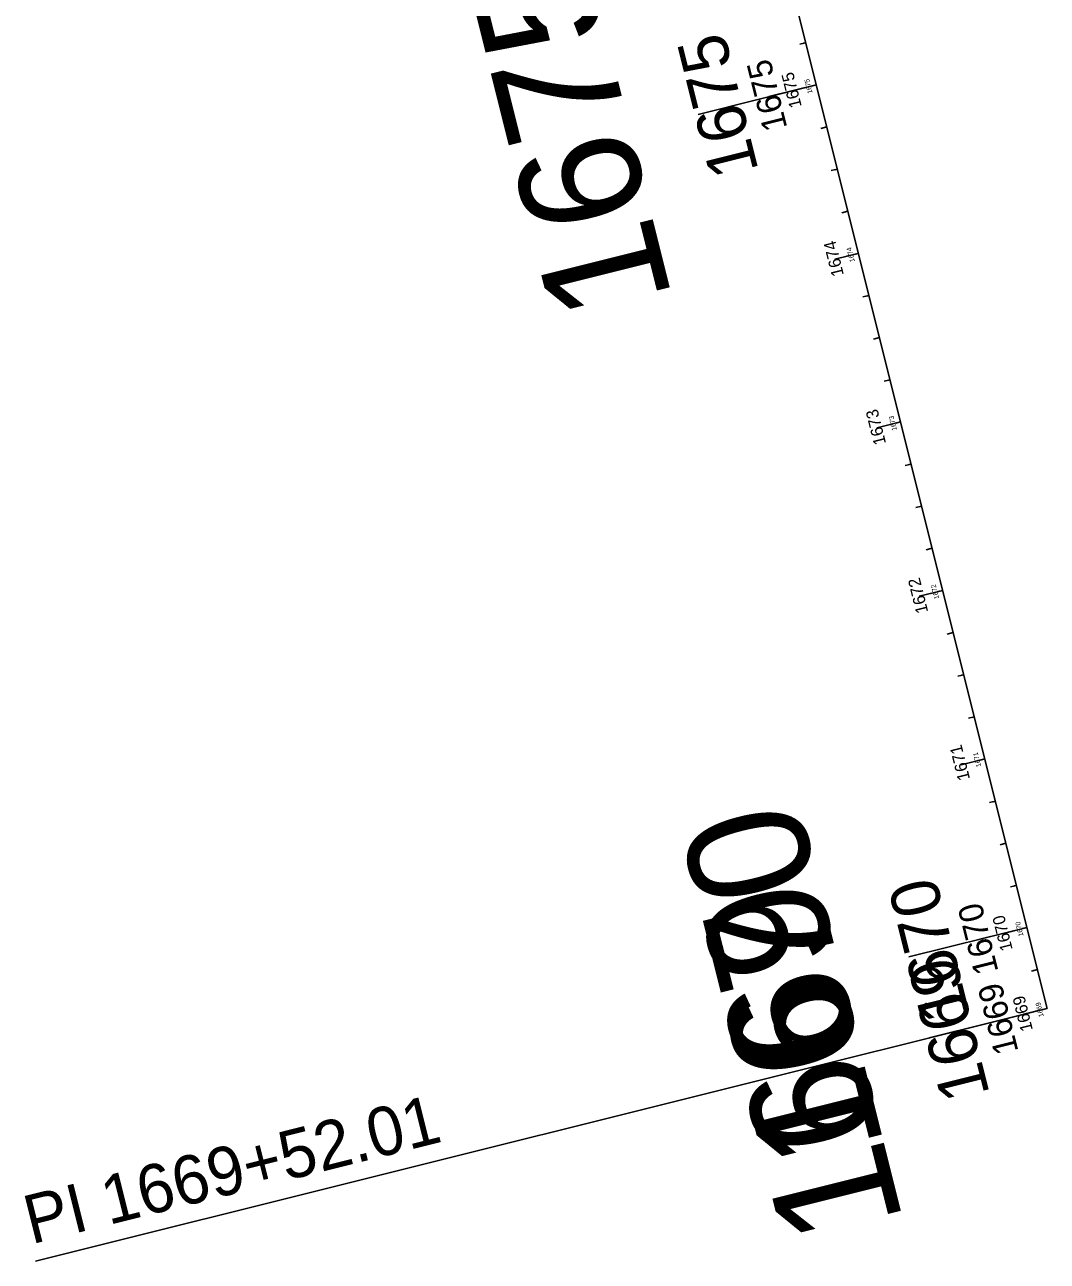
# Model space of a CAD drawing. Extents: x 353835 to 363333, y 126218 to 205387.
# Drawn here: x 361909 to 362497, y 126218 to 126930 of the extents above; entities that cross this region are included whole.
import ezdxf

# ---------------------------------------------------------------- set-up
doc = ezdxf.new("R2010")
doc.units = 0
for name, color, linetype in [('P_ALI_100_Sta', 7, 'Continuous'), ('P_ALI_100_Tic', 7, 'Continuous'), ('P_ALI_20', 7, 'Continuous'), ('P_ALI_200_PIData', 7, 'Continuous'), ('P_ALI_200_Sta', 7, 'Continuous'), ('P_ALI_200_Tic', 7, 'Continuous'), ('P_ALI_20_Sta', 7, 'Continuous'), ('P_ALI_20_Tic', 7, 'Continuous'), ('P_ALI_500_Sta', 7, 'Continuous'), ('P_ALI_50_Sta', 7, 'Continuous'), ('P_ALI_50_Tic', 7, 'Continuous')]:
    doc.layers.add(name, color=color, linetype=linetype)

msp = doc.modelspace()

# ---------------------------------------------------------------- linework, layer by layer
at = {"layer": 'P_ALI_100_Tic'}
for points in [[(362296.48, 126878.63), (362364.39, 126895.62)], [(362350.81, 126892.22), (362364.39, 126895.62)], [(362381.86, 126796.91), (362388.66, 126798.61)], [(362406.13, 126699.9), (362412.92, 126701.6)], [(362430.4, 126602.89), (362437.19, 126604.59)], [(362454.66, 126505.88), (362461.45, 126507.58)], [(362417.81, 126393.58), (362485.72, 126410.57)], [(362472.14, 126407.17), (362485.72, 126410.57)], [(362429.46, 126347.02), (362497.37, 126364.01)], [(362429.46, 126347.02), (362497.37, 126364.01)], [(362483.78, 126360.61), (362497.37, 126364.01)], [(362483.78, 126360.61), (362497.37, 126364.01)]]:
    msp.add_lwpolyline(points, dxfattribs=at)
at = {"layer": 'P_ALI_20'}
msp.add_line((362497.37, 126364.01), (362263.22, 127300.08), dxfattribs=at)
at = {"layer": 'P_ALI_200_PIData'}
msp.add_lwpolyline([(362497.37, 126364.01), (361915.3, 126218.41)], dxfattribs=at)
at = {"layer": 'P_ALI_200_Tic'}
for points in [[(362337.23, 126888.83), (362364.39, 126895.62)], [(362375.07, 126795.21), (362388.66, 126798.61)], [(362399.34, 126698.2), (362412.92, 126701.6)], [(362423.61, 126601.19), (362437.19, 126604.59)], [(362447.87, 126504.18), (362461.45, 126507.58)], [(362458.56, 126403.77), (362485.72, 126410.57)], [(362470.2, 126357.22), (362497.37, 126364.01)], [(362470.2, 126357.22), (362497.37, 126364.01)]]:
    msp.add_lwpolyline(points, dxfattribs=at)
at = {"layer": 'P_ALI_20_Tic'}
for points in [[(362356.96, 126919.53), (362358.32, 126919.87)], [(362361.67, 126894.94), (362364.39, 126895.62)], [(362369.1, 126871.03), (362370.46, 126871.37)], [(362375.16, 126846.78), (362376.52, 126847.12)], [(362381.23, 126822.52), (362382.59, 126822.86)], [(362385.94, 126797.93), (362388.66, 126798.61)], [(362393.36, 126774.02), (362394.72, 126774.36)], [(362399.43, 126749.76), (362400.79, 126750.1)], [(362405.5, 126725.51), (362406.85, 126725.85)], [(362410.21, 126700.92), (362412.92, 126701.6)], [(362417.63, 126677.01), (362418.99, 126677.35)], [(362423.7, 126652.75), (362425.05, 126653.09)], [(362429.76, 126628.5), (362431.12, 126628.84)], [(362434.47, 126603.91), (362437.19, 126604.59)], [(362441.9, 126580), (362443.25, 126580.34)], [(362447.96, 126555.74), (362449.32, 126556.08)], [(362454.03, 126531.49), (362455.39, 126531.83)], [(362458.74, 126506.9), (362461.45, 126507.58)], [(362466.16, 126482.98), (362467.52, 126483.32)], [(362472.23, 126458.73), (362473.59, 126459.07)], [(362478.3, 126434.48), (362479.65, 126434.82)], [(362483, 126409.89), (362485.72, 126410.57)], [(362490.43, 126385.97), (362491.79, 126386.31)], [(362494.65, 126363.33), (362497.37, 126364.01)], [(362494.65, 126363.33), (362497.37, 126364.01)]]:
    msp.add_lwpolyline(points, dxfattribs=at)
at = {"layer": 'P_ALI_50_Tic'}
for points in [[(362354.93, 126919.02), (362358.32, 126919.87)], [(362354.93, 126919.02), (362358.32, 126919.87)], [(362357.6, 126893.92), (362364.39, 126895.62)], [(362357.6, 126893.92), (362364.39, 126895.62)], [(362367.06, 126870.52), (362370.46, 126871.37)], [(362367.06, 126870.52), (362370.46, 126871.37)], [(362373.13, 126846.27), (362376.52, 126847.12)], [(362373.13, 126846.27), (362376.52, 126847.12)], [(362379.19, 126822.01), (362382.59, 126822.86)], [(362379.19, 126822.01), (362382.59, 126822.86)], [(362381.86, 126796.91), (362388.66, 126798.61)], [(362381.86, 126796.91), (362388.66, 126798.61)], [(362391.33, 126773.51), (362394.72, 126774.36)], [(362391.33, 126773.51), (362394.72, 126774.36)], [(362397.39, 126749.26), (362400.79, 126750.1)], [(362397.39, 126749.26), (362400.79, 126750.1)], [(362403.46, 126725), (362406.85, 126725.85)], [(362403.46, 126725), (362406.85, 126725.85)], [(362406.13, 126699.9), (362412.92, 126701.6)], [(362406.13, 126699.9), (362412.92, 126701.6)], [(362415.59, 126676.5), (362418.99, 126677.35)], [(362415.59, 126676.5), (362418.99, 126677.35)], [(362421.66, 126652.24), (362425.05, 126653.09)], [(362421.66, 126652.24), (362425.05, 126653.09)], [(362427.73, 126627.99), (362431.12, 126628.84)], [(362427.73, 126627.99), (362431.12, 126628.84)], [(362430.4, 126602.89), (362437.19, 126604.59)], [(362430.4, 126602.89), (362437.19, 126604.59)], [(362439.86, 126579.49), (362443.25, 126580.34)], [(362439.86, 126579.49), (362443.25, 126580.34)], [(362445.93, 126555.23), (362449.32, 126556.08)], [(362445.93, 126555.23), (362449.32, 126556.08)], [(362451.99, 126530.98), (362455.39, 126531.83)], [(362451.99, 126530.98), (362455.39, 126531.83)], [(362454.66, 126505.88), (362461.45, 126507.58)], [(362454.66, 126505.88), (362461.45, 126507.58)], [(362464.13, 126482.47), (362467.52, 126483.32)], [(362464.13, 126482.47), (362467.52, 126483.32)], [(362470.19, 126458.22), (362473.59, 126459.07)], [(362470.19, 126458.22), (362473.59, 126459.07)], [(362476.26, 126433.97), (362479.65, 126434.82)], [(362476.26, 126433.97), (362479.65, 126434.82)], [(362478.93, 126408.87), (362485.72, 126410.57)], [(362478.93, 126408.87), (362485.72, 126410.57)], [(362488.39, 126385.46), (362491.79, 126386.31)], [(362488.39, 126385.46), (362491.79, 126386.31)], [(362490.57, 126362.31), (362497.37, 126364.01)], [(362490.57, 126362.31), (362497.37, 126364.01)], [(362490.57, 126362.31), (362497.37, 126364.01)], [(362490.57, 126362.31), (362497.37, 126364.01)]]:
    msp.add_lwpolyline(points, dxfattribs=at)

# ---------------------------------------------------------------- texts
at = {"layer": 'P_ALI_100_Sta'}
for s, p in [('1675', (362347.89, 126870.93)), ('1670', (362469.35, 126385.34)), ('1669', (362480.86, 126339.32)), ('1669', (362480.86, 126339.32))]:
    msp.add_text(s, height=14, rotation=104.04371, dxfattribs=at).set_placement(p)
at = {"layer": 'P_ALI_200_PIData'}
msp.add_text('PI 1669+52.01', height=28, rotation=14.04371, dxfattribs=at).set_placement((361912.87, 126228.11))
at = {"layer": 'P_ALI_200_Sta'}
for s, p in [('1675', (362331.39, 126846.23)), ('1670', (362452.99, 126360.11)), ('1669', (362464.36, 126314.62)), ('1669', (362464.36, 126314.62))]:
    msp.add_text(s, height=28, rotation=104.04371, dxfattribs=at).set_placement(p)
at = {"layer": 'P_ALI_20_Sta'}
for s, p in [('1675', (362362.37, 126891)), ('1674', (362386.64, 126793.99)), ('1673', (362410.9, 126696.98)), ('1672', (362435.17, 126599.97)), ('1671', (362459.35, 126503.3)), ('1670', (362483.73, 126405.84)), ('1669', (362495.35, 126359.39)), ('1669', (362495.35, 126359.39))]:
    msp.add_text(s, height=2.8, rotation=104.04371, dxfattribs=at).set_placement(p)
at = {"layer": 'P_ALI_500_Sta'}
for s, p in [('1675', (362281.89, 126772.15)), ('1670', (362403.89, 126284.42)), ('1669', (362414.86, 126240.54)), ('1669', (362414.86, 126240.54))]:
    msp.add_text(s, height=70, rotation=104.04371, dxfattribs=at).set_placement(p)
at = {"layer": 'P_ALI_50_Sta'}
for s, p in [('1675', (362356.14, 126883.27)), ('1675', (362356.14, 126883.27)), ('1674', (362380.4, 126786.26)), ('1674', (362380.4, 126786.26)), ('1673', (362404.67, 126689.25)), ('1673', (362404.67, 126689.25)), ('1672', (362428.94, 126592.24)), ('1672', (362428.94, 126592.24)), ('1671', (362452.99, 126496.08)), ('1671', (362452.99, 126496.08)), ('1670', (362477.54, 126397.95)), ('1670', (362477.54, 126397.95)), ('1669', (362489.12, 126351.66)), ('1669', (362489.12, 126351.66)), ('1669', (362489.12, 126351.66)), ('1669', (362489.12, 126351.66))]:
    msp.add_text(s, height=7, rotation=104.04371, dxfattribs=at).set_placement(p)

doc.saveas('drawing.dxf')
